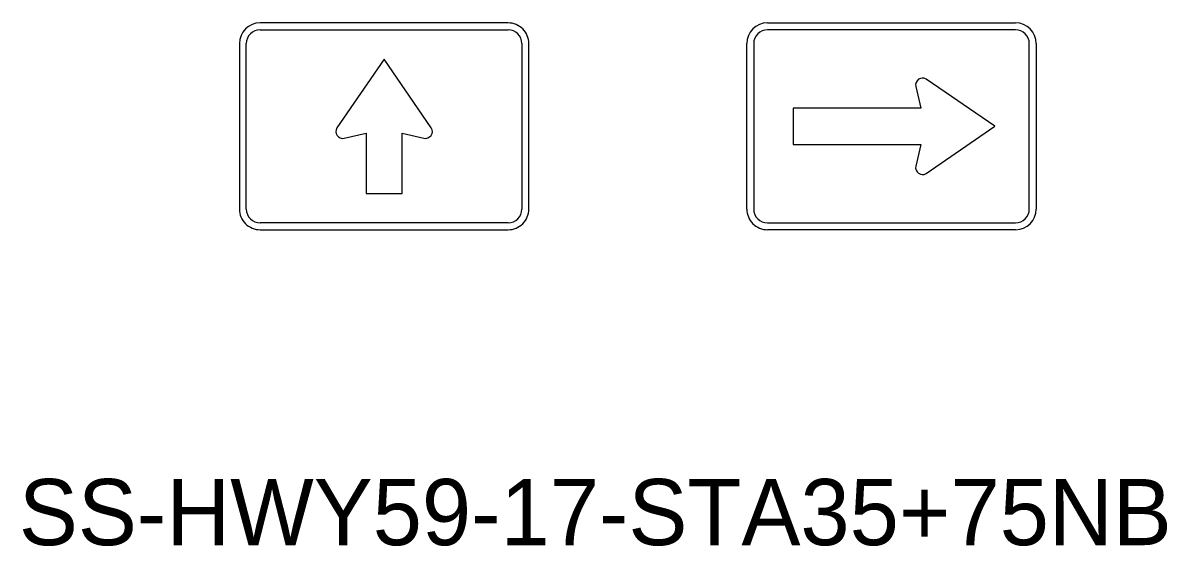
# Model space of a CAD drawing. Extents: x 620856.8 to 620948.6, y 415598.8 to 415658.2.
# Drawn here: x 620879.68 to 620886.6, y 415634.27 to 415637.43 of the extents above; entities that cross this region are included whole.
import ezdxf

# ---------------------------------------------------------------- set-up
doc = ezdxf.new("R2010")
doc.units = 0
doc.layers.add('SIGNS', color=7, linetype='Continuous')

msp = doc.modelspace()

# ---------------------------------------------------------------- linework, layer by layer
at = {"layer": 'SIGNS'}
for p, q in [((620882.6126, 415637.4316), (620881.1126, 415637.4316)), ((620881.1126, 415637.39), (620882.6126, 415637.39)), ((620884.1806, 415637.4316), (620885.6806, 415637.4316)), ((620885.6806, 415637.39), (620884.1806, 415637.39)), ((620885.6806, 415637.4316), (620885.6806, 415637.4316)), ((620880.9876, 415637.3066), (620880.9876, 415636.3066)), ((620881.0293, 415636.3066), (620881.0293, 415637.3066)), ((620882.6959, 415637.3066), (620882.6959, 415636.3066)), ((620882.7376, 415636.3066), (620882.7376, 415637.3066)), ((620884.0556, 415636.3066), (620884.0556, 415637.3066)), ((620884.0973, 415637.3066), (620884.0973, 415636.3066)), ((620885.7639, 415636.3066), (620885.7639, 415637.3066)), ((620885.8056, 415637.3066), (620885.8056, 415636.3066)), ((620881.8626, 415637.2129), (620881.5774, 415636.7976)), ((620882.1478, 415636.7976), (620881.8626, 415637.2129)), ((620885.5556, 415636.8066), (620885.1403, 415637.0919)), ((620885.0775, 415637.0473), (620885.1077, 415636.916)), ((620885.1077, 415636.916), (620884.3368, 415636.916)), ((620884.3368, 415636.916), (620884.3368, 415636.6973)), ((620881.6219, 415636.7348), (620881.7532, 415636.765)), ((620881.7532, 415636.765), (620881.7532, 415636.4004)), ((620881.972, 415636.4004), (620881.972, 415636.765)), ((620881.972, 415636.765), (620882.1033, 415636.7348)), ((620885.1403, 415636.5214), (620885.5556, 415636.8066)), ((620884.3368, 415636.6973), (620885.1077, 415636.6973)), ((620885.1077, 415636.6973), (620885.0775, 415636.566)), ((620881.7532, 415636.4004), (620881.972, 415636.4004)), ((620882.6126, 415636.2233), (620881.1126, 415636.2233)), ((620884.1806, 415636.2233), (620885.6806, 415636.2233)), ((620881.1126, 415636.1816), (620882.6126, 415636.1816)), ((620885.6806, 415636.1816), (620884.1806, 415636.1816)), ((620884.1806, 415636.1816), (620884.1806, 415636.1816))]:
    msp.add_line(p, q, dxfattribs=at)
for points in [[(620884.1806, 415637.4316), (620884.1806, 415637.4316)], [(620884.0556, 415637.3066), (620884.0556, 415637.3066)], [(620885.8056, 415636.3066), (620885.8056, 415636.3066)], [(620885.6806, 415636.1816), (620885.6806, 415636.1816)]]:
    msp.add_lwpolyline(points, dxfattribs=at)
for centre, radius, start, end in [((620881.1126, 415637.3066), 0.125, 90.00021, 179.99985), ((620881.1126, 415637.3066), 0.0833, 90.00021, 179.99985), ((620882.6126, 415637.3066), 0.125, 360, 90.00021), ((620882.6126, 415637.3066), 0.0833, 360, 90.00021), ((620884.1806, 415637.3066), 0.125, 90.00021, 179.99985), ((620884.1806, 415637.3066), 0.0833, 90.00021, 179.99985), ((620885.6806, 415637.3066), 0.125, 0, 90), ((620885.6806, 415637.3066), 0.0833, 0, 90.00021), ((620885.1181, 415637.0566), 0.0417, 57.72435, 192.95041), ((620881.6126, 415636.7754), 0.0417, 147.72456, 282.95062), ((620882.1126, 415636.7754), 0.0417, 257.04949, 32.27555), ((620885.1181, 415636.5566), 0.0417, 167.04986, 302.27592), ((620881.1126, 415636.3066), 0.125, 179.99985, 270.00006), ((620881.1126, 415636.3066), 0.0833, 179.99985, 270.00006), ((620882.6126, 415636.3066), 0.125, 270.00006, 0.00027), ((620882.6126, 415636.3066), 0.0833, 270.00006, 0.00027), ((620884.1806, 415636.3066), 0.125, 179.99985, 270), ((620884.1806, 415636.3066), 0.0833, 179.99985, 270.00006), ((620885.6806, 415636.3066), 0.125, 270.00006, 360), ((620885.6806, 415636.3066), 0.0833, 270.00006, 0.00027)]:
    msp.add_arc(centre, radius, start, end, dxfattribs=at)

# ---------------------------------------------------------------- texts
msp.add_text('SS-HWY59-17-STA35+75NB', height=0.4, rotation=0, dxfattribs=at).set_placement((620879.6541, 415634.2755))

doc.saveas('drawing.dxf')
